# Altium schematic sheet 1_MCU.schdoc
size A3; Symbol: Sheet-Symbol_A4; Device: Sheet-Symbol_A4; Company: 嘉立创EDA; Version: V1.0; Page Size: A4; @Project Name: 基于STM32的四旋翼无人机控制系统设计; @Page Count: 2; @Update Date: 2025-04-11; @Create Date: 2025-04-05; @Schematic Name: 基于STM32的无人机控制系统设计_AK09915; @Page No: 1; @Page Name: MCU; @Board Name: 基于STM32的无人机控制系统设计_AK09915; @Create Time: 23:31:03; @Update Time: 20:13:46; Width: 1170; Height: 825; Region Start: 1; X Region Count: 6; Y Region Count: 4; Blade Width: 10; Title Block Position: 3
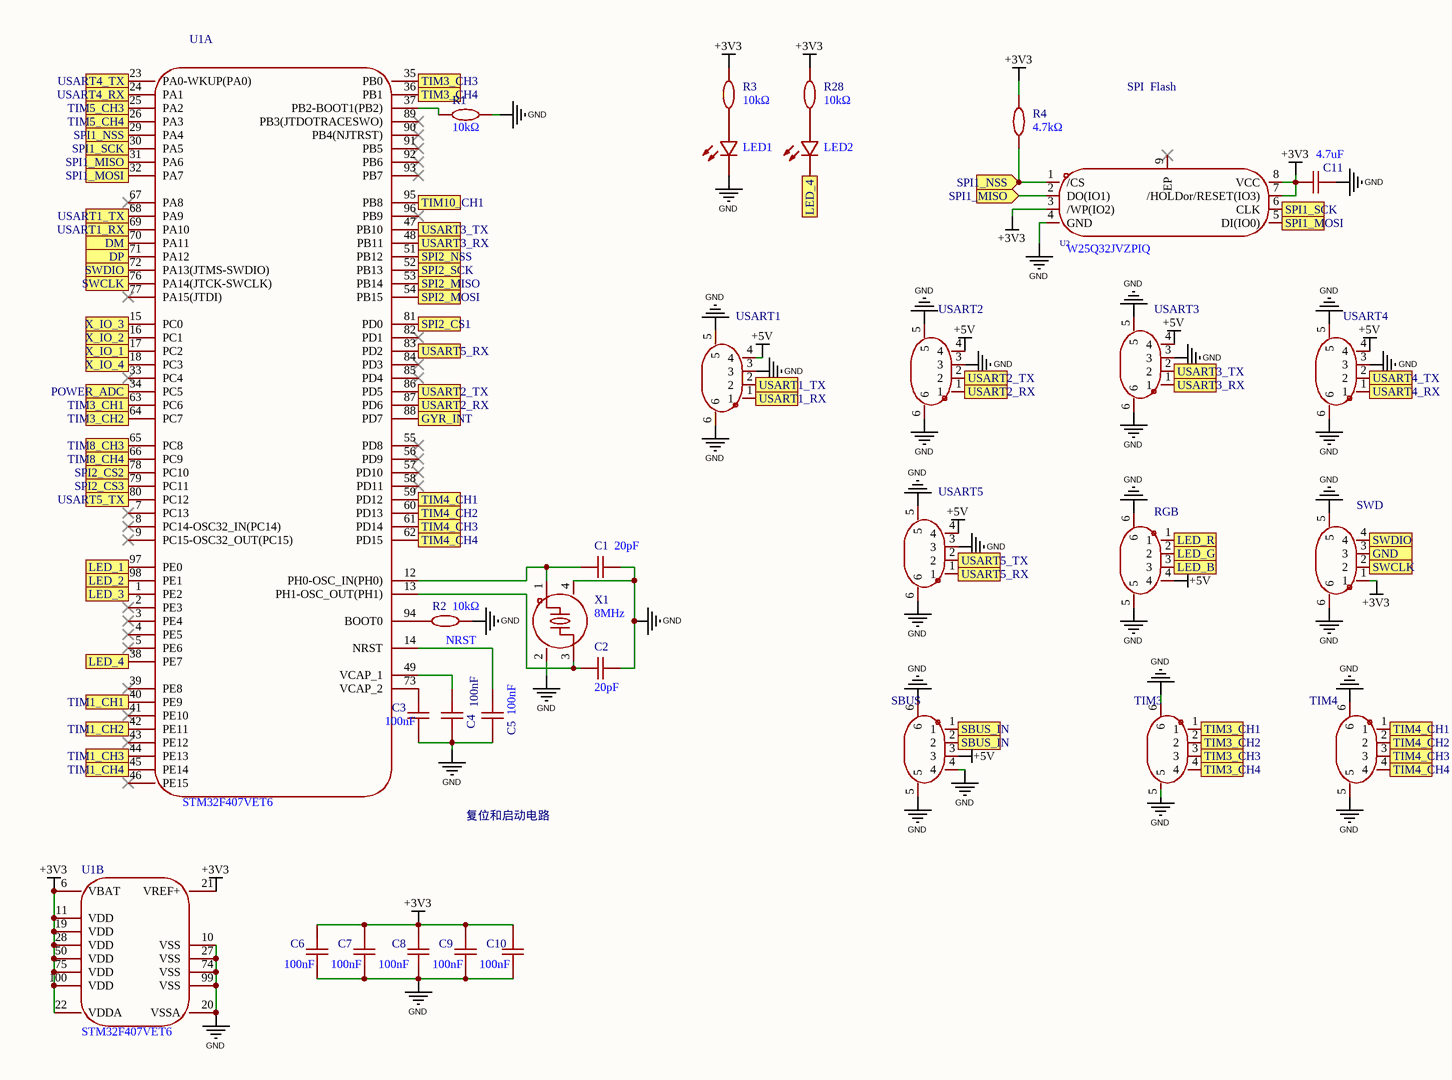
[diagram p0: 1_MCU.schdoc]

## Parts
C1  20pF  [C0603]
C2  20pF  [C0603]
C3  100nF  [C0603]
C4  100nF  [C0603]
C5  100nF  [C0603]
C6  100nF  [C0603]
C7  100nF  [C0603]
C8  100nF  [C0603]
C9  100nF  [C0603]
C10  100nF  [C0603]
C11  4.7uF  [C0603]
LED1  19-213/Y2C-CQ2R2L/3T(CY)  [LED0603-RD-YELLOW]  (value not drawn)
LED2  19-213/Y2C-CQ2R2L/3T(CY)  [LED0603-RD-YELLOW]  (value not drawn)
R1  10kΩ  [R0603]
R2  10kΩ  [R0603]
R3  10kΩ  [R0603]
R4  4.7kΩ  [R0603]
R28  10kΩ  [R0603]
RGB  ZX-SH1.0-4PWT  [CONN-SMD_4P-P1.00_MEGASTAR_ZX-SH1.0-4PWT]  (value not drawn)
SBUS  ZX-SH1.0-4PWT  [CONN-SMD_4P-P1.00_MEGASTAR_ZX-SH1.0-4PWT]  (value not drawn)
SWD  ZX-SH1.0-4PWT  [CONN-SMD_4P-P1.00_MEGASTAR_ZX-SH1.0-4PWT]  (value not drawn)
TIM3  ZX-SH1.0-4PWT  [CONN-SMD_4P-P1.00_MEGASTAR_ZX-SH1.0-4PWT]  (value not drawn)
TIM4  ZX-SH1.0-4PWT  [CONN-SMD_4P-P1.00_MEGASTAR_ZX-SH1.0-4PWT]  (value not drawn)
U1  STM32F407VET6  [LQFP-100_L14.0-W14.0-P0.50-LS16.0-BL]  (parts A,B of 2)
U2  W25Q32JVZPIQ  [WSON-8_L6.0-W5.0-P1.27-BL-EP]
USART1  ZX-SH1.0-4PWT  [CONN-SMD_4P-P1.00_MEGASTAR_ZX-SH1.0-4PWT]  (value not drawn)
USART2  ZX-SH1.0-4PWT  [CONN-SMD_4P-P1.00_MEGASTAR_ZX-SH1.0-4PWT]  (value not drawn)
USART3  ZX-SH1.0-4PWT  [CONN-SMD_4P-P1.00_MEGASTAR_ZX-SH1.0-4PWT]  (value not drawn)
USART4  ZX-SH1.0-4PWT  [CONN-SMD_4P-P1.00_MEGASTAR_ZX-SH1.0-4PWT]  (value not drawn)
USART5  ZX-SH1.0-4PWT  [CONN-SMD_4P-P1.00_MEGASTAR_ZX-SH1.0-4PWT]  (value not drawn)
X1  8MHz  [OSC-SMD_4P-L3.2-W2.5-BL]

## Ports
DM (in), DP (in), GND (in), GYR_INT (in), LED_1 (in), LED_2 (in), LED_3 (in), LED_4 (in), LED_B (in), LED_G (in), LED_R (in), POWER_ADC (in), SBUS_IN (in), SPI1_MISO (in), SPI1_MOSI (in), SPI1_NSS (in), SPI1_SCK (in), SPI2_CS1 (in), SPI2_CS2 (in), SPI2_CS3 (in), SPI2_MISO (in), SPI2_MOSI (in), SPI2_NSS (in), SPI2_SCK (in), SWCLK (in), SWDIO (in), TIM1_CH1 (in), TIM1_CH2 (in), TIM1_CH3 (in), TIM1_CH4 (in), TIM3_CH1 (in), TIM3_CH2 (in), TIM3_CH3 (in), TIM3_CH4 (in), TIM4_CH1 (in), TIM4_CH2 (in), TIM4_CH3 (in), TIM4_CH4 (in), TIM5_CH3 (in), TIM5_CH4 (in), TIM8_CH3 (in), TIM8_CH4 (in), TIM10_CH1 (in), USART1_RX (in), USART1_TX (in), USART2_RX (in), USART2_TX (in), USART3_RX (in), USART3_TX (in), USART4_RX (in), USART4_TX (in), USART5_RX (in), USART5_TX (in), X_IO_1 (in), X_IO_2 (in), X_IO_3 (in), X_IO_4 (in)

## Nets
+3V3: C6.2 C7.2 C8.2 C9.2 C10.2 C11.1 R3.2 R4.2 R28.2 SWD.1 U1.6(VBAT) U1.11(VDD) U1.19(VDD) U1.21(VREF+) U1.22(VDDA) U1.28(VDD) U1.50(VDD) U1.75(VDD) U1.100(VDD) U2.3(/WP(IO2)) U2.7(/HOLDor/RESET(IO3)) U2.8(VCC)
+5V: RGB.4 SBUS.3 USART1.4 USART2.4 USART3.4 USART4.4 USART5.4
GND: C1.1 C2.1 C3.1 C4.1 C5.1 C6.1 C7.1 C8.1 C9.1 C10.1 C11.2 LED1.1(C) R1.2 R2.2 RGB.5 RGB.6 SBUS.4 SBUS.5 SBUS.6 SWD.5 SWD.6 TIM3.5 TIM3.6 TIM4.5 TIM4.6 U1.10(VSS) U1.20(VSSA) U1.27(VSS) U1.74(VSS) U1.99(VSS) U2.4(GND) USART1.3 USART1.5 USART1.6 USART2.3 USART2.5 USART2.6 USART3.3 USART3.5 USART3.6 USART4.3 USART4.5 USART4.6 USART5.3 USART5.5 USART5.6 X1.2(GND) X1.4(GND)
DM: U1.70(PA11) ; port DM
DP: U1.71(PA12) ; port DP
GND: SWD.3 ; port GND  [a separate net that carries the same name]
GYR_INT: U1.88(PD7) ; port GYR_INT
LED_1: U1.97(PE0) ; port LED_1
LED_2: U1.98(PE1) ; port LED_2
LED_3: U1.1(PE2) ; port LED_3
LED_4: LED2.1(C) U1.38(PE7) ; port LED_4
LED_B: RGB.3 ; port LED_B
LED_G: RGB.2 ; port LED_G
LED_R: RGB.1 ; port LED_R
NRST: C5.2 U1.14(NRST)
POWER_ADC: U1.34(PC5) ; port POWER_ADC
SBUS_IN: SBUS.1 SBUS.2 ; port SBUS_IN
SPI1_MISO: U1.31(PA6) U2.2(DO(IO1)) ; port SPI1_MISO
SPI1_MOSI: U1.32(PA7) U2.5(DI(IO0)) ; port SPI1_MOSI
SPI1_NSS: R4.1 U1.29(PA4) U2.1(/CS) ; port SPI1_NSS
SPI1_SCK: U1.30(PA5) U2.6(CLK) ; port SPI1_SCK
SPI2_CS1: U1.81(PD0) ; port SPI2_CS1
SPI2_CS2: U1.78(PC10) ; port SPI2_CS2
SPI2_CS3: U1.79(PC11) ; port SPI2_CS3
SPI2_MISO: U1.53(PB14) ; port SPI2_MISO
SPI2_MOSI: U1.54(PB15) ; port SPI2_MOSI
SPI2_NSS: U1.51(PB12) ; port SPI2_NSS
SPI2_SCK: U1.52(PB13) ; port SPI2_SCK
SWCLK: SWD.2 U1.76(PA14(JTCK-SWCLK)) ; port SWCLK
SWDIO: SWD.4 U1.72(PA13(JTMS-SWDIO)) ; port SWDIO
TIM1_CH1: U1.40(PE9) ; port TIM1_CH1
TIM1_CH2: U1.42(PE11) ; port TIM1_CH2
TIM1_CH3: U1.44(PE13) ; port TIM1_CH3
TIM1_CH4: U1.45(PE14) ; port TIM1_CH4
TIM3_CH1: TIM3.1 U1.63(PC6) ; port TIM3_CH1
TIM3_CH2: TIM3.2 U1.64(PC7) ; port TIM3_CH2
TIM3_CH3: TIM3.3 U1.35(PB0) ; port TIM3_CH3
TIM3_CH4: TIM3.4 U1.36(PB1) ; port TIM3_CH4
TIM4_CH1: TIM4.1 U1.59(PD12) ; port TIM4_CH1
TIM4_CH2: TIM4.2 U1.60(PD13) ; port TIM4_CH2
TIM4_CH3: TIM4.3 U1.61(PD14) ; port TIM4_CH3
TIM4_CH4: TIM4.4 U1.62(PD15) ; port TIM4_CH4
TIM5_CH3: U1.25(PA2) ; port TIM5_CH3
TIM5_CH4: U1.26(PA3) ; port TIM5_CH4
TIM8_CH3: U1.65(PC8) ; port TIM8_CH3
TIM8_CH4: U1.66(PC9) ; port TIM8_CH4
TIM10_CH1: U1.95(PB8) ; port TIM10_CH1
USART1_RX: U1.69(PA10) USART1.1 ; port USART1_RX
USART1_TX: U1.68(PA9) USART1.2 ; port USART1_TX
USART2_RX: U1.87(PD6) USART2.1 ; port USART2_RX
USART2_TX: U1.86(PD5) USART2.2 ; port USART2_TX
USART3_RX: U1.48(PB11) USART3.1 ; port USART3_RX
USART3_TX: U1.47(PB10) USART3.2 ; port USART3_TX
USART4_RX: U1.24(PA1) USART4.1 ; port USART4_RX
USART4_TX: U1.23(PA0-WKUP(PA0)) USART4.2 ; port USART4_TX
USART5_RX: U1.83(PD2) USART5.1 ; port USART5_RX
USART5_TX: U1.80(PC12) USART5.2 ; port USART5_TX
X_IO_1: U1.17(PC2) ; port X_IO_1
X_IO_2: U1.16(PC1) ; port X_IO_2
X_IO_3: U1.15(PC0) ; port X_IO_3
X_IO_4: U1.18(PC3) ; port X_IO_4
NetC1_2: C1.2 U1.12(PH0-OSC_IN(PH0)) X1.1
NetC2_2: C2.2 U1.13(PH1-OSC_OUT(PH1)) X1.3
NetC3_2: C3.2 U1.73(VCAP_2)
NetC4_2: C4.2 U1.49(VCAP_1)
NetLED1_2: LED1.2(A) R3.1
NetLED2_2: LED2.2(A) R28.1
NetR1_1: R1.1 U1.37(PB2-BOOT1(PB2))
NetR2_1: R2.1 U1.94(BOOT0)

Not connected (* = marked no-connect by the designer): U1 2(PE3)* 3(PE4)* 4(PE5)* 5(PE6)* 7(PC13)* 8(PC14-OSC32_IN(PC14))* 9(PC15-OSC32_OUT(PC15))* 33(PC4)* 39(PE8)* 41(PE10)* 43(PE12)* 46(PE15)* 55(PD8)* 56(PD9)* 57(PD10)* 58(PD11)* 67(PA8)* 77(PA15(JTDI))* 82(PD1)* 84(PD3)* 85(PD4)* 89(PB3(JTDOTRACESWO))* 90(PB4(NJTRST))* 91(PB5)* 92(PB6)* 93(PB7)* 96(PB9)*; U2 9(EP)*

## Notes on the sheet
- MCU
- SPI  Flash
- 复位和启动电路

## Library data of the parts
C1 C2 = CL10C200JB8NNNC: Manufacturer: SAMSUNG(三星); Add into BOM: yes; Tolerance: ±5%; Voltage Rated: 50V; Temperature Coefficient: C0G
C3-C10 = CC0603KRX7R9BB104: Manufacturer: YAGEO(国巨); Add into BOM: yes; Tolerance: ±10%; Voltage Rated: 50V; Temperature Coefficient: X7R
C11 = CL10A475KO8NNNC: Manufacturer: SAMSUNG(三星); Add into BOM: yes; Tolerance: ±10%; Voltage Rated: 16V; Temperature Coefficient: X5R
LED1 LED2 = 19-213/Y2C-CQ2R2L/3T(CY): Manufacturer: EVERLIGHT(亿光); Add into BOM: yes; Emitted Color: 黄色; Power Dissipation: 60mW; Forward Current: 20mA; Dominant Wavelength: 585.5nm~591.5nm; Peak Wavelength: 591nm; Lens Color: 无色透明透镜; Viewing Angle: 120°
R1-R3 R28 = 0603WAF1002T5E: Manufacturer: UNI-ROYAL(厚声); Add into BOM: yes; Tolerance: ±1%; Power(Watts): 100mW; Overload Voltage (Max): 75V; Temperature Coefficient: ±100ppm/℃
R4 = 0603WAF4701T5E: Manufacturer: UNI-ROYAL(厚声); Add into BOM: yes; Tolerance: ±1%; Power(Watts): 100mW; Overload Voltage (Max): 75V; Temperature Coefficient: ±100ppm/℃
RGB SBUS SWD TIM3 TIM4 USART1-USART5 = ZX-SH1.0-4PWT: Manufacturer: Megastar(兆星); Add into BOM: yes; Pins Structure: 1x4P; Pitch: 1mm; Reference Series: SH; Number of PINs Per Row: 4; Current Rating (Max): 1A
U1 = STM32F407VET6: Manufacturer: ST(意法半导体); Add into BOM: yes; CPU Core: ARM-M4; Program Storage Size: 512KB; RAM Size: 192KB; GPIO Ports Number: 82; Operating Voltage Range: 1.8V~3.6V; CPU Maximum Speed: 168MHz; Program Memory Type: FLASH; ADC (Bit): 12bit; Universal Serial Bus: 有; Peripheral/Function: DMA；LCD/LED驱动；PWM; Relevance: []
U2 = W25Q32JVZPIQ: Manufacturer: WINBOND(华邦); Add into BOM: yes
X1 = X32258MOB4SI: Manufacturer: YXC(扬兴晶振); Add into BOM: yes; Crystal Type: 贴片晶振; Normal temperature Frequency Tolerance: ±10ppm; External load capacitor: 12pF; Frequency Stability(Full temperature range): ±20ppm; Equivalent Series Resistance (ESR): 150Ω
